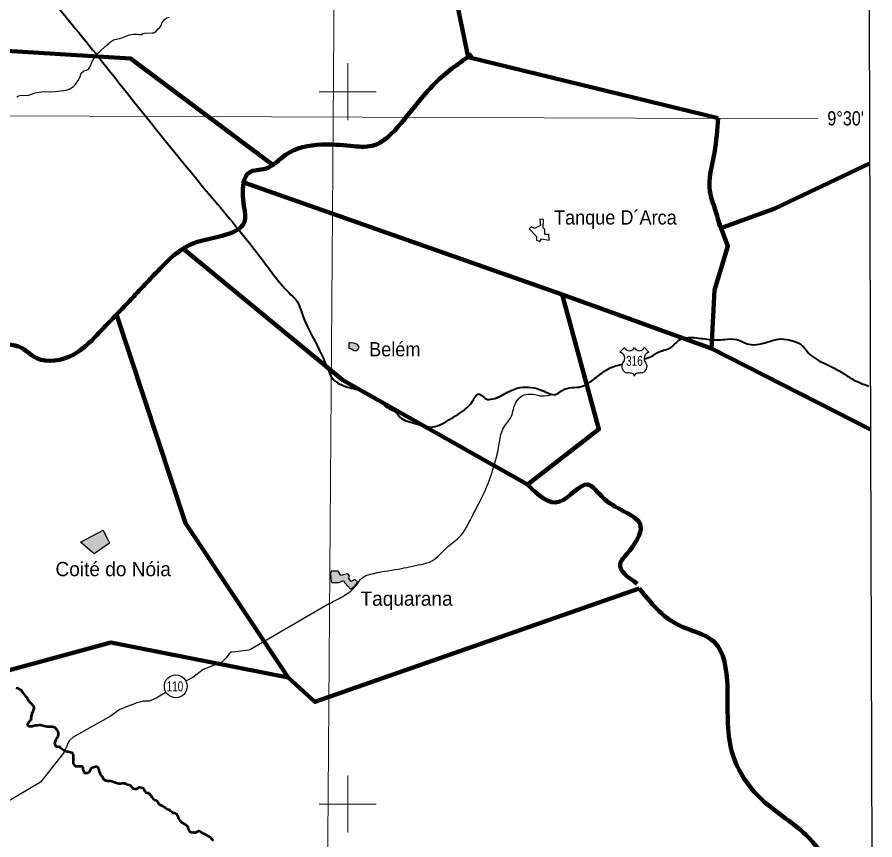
# Model space of a CAD drawing. Extents: x 553962 to 842807, y 8883888 to 9032388.
# Drawn here: x 763398 to 793496, y 8923744 to 8952617 of the extents above; entities that cross this region are included whole.
import ezdxf
from ezdxf.enums import TextEntityAlignment as Align

# ---------------------------------------------------------------- set-up
doc = ezdxf.new("R2010")
doc.units = 0
doc.header["$LTSCALE"] = 200
for name, color, linetype, lineweight in [('1', 7, 'Continuous', 13), ('12', 7, 'Continuous', 25), ('2', 7, 'Continuous', 13), ('21', 7, 'Continuous', 25), ('24', 7, 'Continuous', 25), ('3', 7, 'Continuous', 80), ('48', 7, 'Continuous', 25), ('9', 7, 'Continuous', 90)]:
    doc.layers.add(name, color=color, linetype=linetype, lineweight=lineweight)
doc.layers.add('41', color=7, linetype='Continuous')
doc.layers.add('46', color=7, linetype='Continuous')

msp = doc.modelspace()

# ---------------------------------------------------------------- hatches: boundary and pattern name
at = {"layer": '21'}
for points in [[(775339.3, 8941128.8), (775228, 8941177.1), (775095.1, 8941191.9), (775050.9, 8941185.2), (775036.1, 8941163.7), (775040.1, 8941107.3), (775033.4, 8941051), (775025.4, 8941018.8), (775064.3, 8940997.3), (775130, 8940970.5), (775194.4, 8940945), (775223.9, 8940916.8), (775309.8, 8940919.5), (775363.5, 8940965.1), (775403.7, 8941040.3)], [(765624.2, 8934185.8), (766418.4, 8934607.9), (766636, 8934155.3), (766095.9, 8933780)], [(774667, 8933172.8), (774418.6, 8933170.5), (774396, 8933082.4), (774400.5, 8932917.5), (774418.6, 8932822.7), (774445.7, 8932775.3), (774698.6, 8932779.8), (774850, 8932843), (774890.6, 8932773), (775098.4, 8932542.6), (775263.3, 8932657.8), (775353.6, 8932782), (775242.9, 8932881.4), (775123.2, 8932806.9), (775037.4, 8932913), (775055.5, 8933010.1), (775003.5, 8933075.6), (774888.3, 8933062.1), (774752.8, 8933019.2)]]:
    msp.add_hatch(color=256, dxfattribs=at).paths.add_polyline_path(points)

# ---------------------------------------------------------------- linework, layer by layer
at = {"layer": '1'}
msp.add_line((565315.3, 8949866.8), (791497.7, 8949052.2), dxfattribs=at)
msp.add_lwpolyline([(774987.1, 9020818), (774482.3, 8948876), (774053.6, 8890875.3)], dxfattribs=at)
at = {"layer": '12'}
for points in [[(774356.7, 8932040.9), (771581.7, 8930420.9), (771525.6, 8930405.7), (771061.8, 8930345.4), (770909, 8930335.5), (770822.1, 8930264.4), (770735, 8930137.2), (770571.4, 8929969.4), (770459.1, 8929908.4), (770367.4, 8929898.4), (769928.6, 8929726), (769560.8, 8929446.5), (769323.7, 8929324.5)], [(768612, 8928917.3), (768391.8, 8928786.5), (768305, 8928730.6), (768213.1, 8928695.1), (768044.7, 8928608.8), (767820.5, 8928609.2), (767703.2, 8928573.8), (767591.1, 8928548.5), (767438, 8928487.7), (767412.6, 8928487.7), (766978.9, 8928310.2), (766697.9, 8928101.9), (765365.5, 8927345.3), (765232.7, 8927233.5), (765181.3, 8927131.7), (765140.2, 8927029.9), (765099.1, 8926933.2), (765047.8, 8926826.3), (764310.7, 8925890.3), (764269.7, 8925824.2), (764213.5, 8925763.2), (763095.4, 8925103)]]:
    msp.add_lwpolyline(points, dxfattribs=at)
at = {"layer": '12', "lineweight": 40}
for points in [[(761549.2, 8957020.4), (762383.1, 8955993.9), (763257, 8954902.9), (764214.4, 8953717.3), (766168.2, 8951324.4), (767086.6, 8950171.6), (770317.8, 8946184.2), (771971, 8944146), (773006.3, 8942876.2), (773223.4, 8942642.3), (773373.7, 8942274.8), (774008.3, 8940921.5), (774359, 8940136.3), (774475.8, 8939919.1), (774642.8, 8939785.5), (774893.3, 8939668.5), (775511.2, 8939484.7), (775928.6, 8939267.5), (776078.9, 8939184), (776379.5, 8938916.7), (776680.1, 8938749.6), (776830.4, 8938582.6), (777398.1, 8938348.7), (777899.1, 8938231.7), (778550.4, 8938482.3), (779134.8, 8938866.6), (779452.1, 8939250.8), (779569, 8939384.5), (779685.9, 8939351.1), (779852.9, 8939217.4), (780086.7, 8939217.4), (780604.3, 8939451.3), (781055.2, 8939618.4), (781439.3, 8939618.4), (781823.3, 8939518.1), (782090.5, 8939401.2), (782290.9, 8939367.8), (782524.7, 8939518.1), (782858.7, 8939618.4), (783192.6, 8939651.8), (783509.9, 8939818.9), (783910.7, 8940119.6), (784278.1, 8940336.8), (784625.2, 8940434.5)], [(785398.3, 8940626.9), (785647.4, 8940704.3), (785931.2, 8940871.4), (786332, 8941021.8), (786615.9, 8941272.4), (787083.5, 8941372.6), (787684.6, 8941305.8), (788219, 8941305.8), (788636.5, 8941305.8), (789070.6, 8941138.7), (789438, 8941138.7), (789855.5, 8941255.7)], [(789855.5, 8941255.7), (790222.9, 8941322.5), (790556.8, 8941272.4), (790907.5, 8941122), (791208.1, 8940787.9), (791792.6, 8940437), (792326.9, 8940153), (792694.3, 8939919.1), (793278.8, 8939668.5)]]:
    msp.add_spline(points, degree=3, dxfattribs=at)
at = {"layer": '12'}
msp.add_spline([(774356.7, 8932040.9), (774893.9, 8932329.3), (775282.4, 8932656.4), (775507.2, 8932942.7), (775793.5, 8933065.3), (776774.8, 8933249.3), (777572.2, 8933412.9), (777960.7, 8933535.6), (778451.3, 8933985.3), (778901.1, 8934353.3), (779350.9, 8935068.9), (779841.6, 8936050.3), (780127.8, 8936847.6), (780291.4, 8937501.9), (780393.6, 8938033.4), (780516.3, 8938278.8), (780720.7, 8938565), (780863.8, 8939014.8), (781047.8, 8939280.6), (781477.2, 8939382.8), (781824.8, 8939321.5), (782163.7, 8939377.8)], degree=3, dxfattribs=at)
at = {"layer": '2'}
for p, q in [((775000, 8949000), (775000, 8951000)), ((774000, 8950000), (776000, 8950000)), ((775000, 8924000), (775000, 8926000)), ((774000, 8925000), (776000, 8925000))]:
    msp.add_line(p, q, dxfattribs=at)
at = {"layer": '21'}
for points in [[(782068, 8944791.6), (782057.7, 8944984.8), (781912.3, 8944989.1), (781919.3, 8945159.5), (781854.8, 8945223), (781863, 8945498.7), (781863.2, 8945516.3), (781743, 8945525.3), (781760.5, 8945307), (781556.3, 8945201.7), (781439.1, 8945255.8), (781368.2, 8945189.1), (781618.3, 8944920.1), (781624.3, 8944789.7), (781739.1, 8944748.1), (781797.8, 8944840.2)], [(775339.3, 8941128.8), (775228, 8941177.1), (775095.1, 8941191.9), (775050.9, 8941185.2), (775036.1, 8941163.7), (775040.1, 8941107.3), (775033.4, 8941051), (775025.4, 8941018.8), (775064.3, 8940997.3), (775130, 8940970.5), (775194.4, 8940945), (775223.9, 8940916.8), (775309.8, 8940919.5), (775363.5, 8940965.1), (775403.7, 8941040.3)], [(765624.2, 8934185.8), (766418.4, 8934607.9), (766636, 8934155.3), (766095.9, 8933780)], [(774667, 8933172.8), (774418.6, 8933170.5), (774396, 8933082.4), (774400.5, 8932917.5), (774418.6, 8932822.7), (774445.7, 8932775.3), (774698.6, 8932779.8), (774850, 8932843), (774890.6, 8932773), (775098.4, 8932542.6), (775263.3, 8932657.8), (775353.6, 8932782), (775242.9, 8932881.4), (775123.2, 8932806.9), (775037.4, 8932913), (775055.5, 8933010.1), (775003.5, 8933075.6), (774888.3, 8933062.1), (774752.8, 8933019.2)]]:
    msp.add_lwpolyline(points, close=True, dxfattribs=at)
at = {"layer": '24'}
for points in [[(768186, 8952066.6), (768216.9, 8952077), (768276.8, 8952125.6), (768349.5, 8952201.8), (768405, 8952249), (768448.6, 8952322.2), (768492.5, 8952435.6), (768528.1, 8952482.7), (768574.2, 8952530.8), (768613.3, 8952565.3), (768657.1, 8952591.4), (768749.7, 8952621.2)], [(763389.4, 8949825.8), (763440.7, 8949858.6), (763555.2, 8949879.5), (763767.2, 8949868.9), (763967.1, 8949936), (764029.1, 8949960.5), (764080.2, 8949974.5), (764174.7, 8949982.8), (764331.6, 8950003.9), (764575.5, 8950000), (764735.9, 8950008.2), (765114.3, 8950055), (765220.7, 8950084.3), (765370.3, 8950178.2), (765443.7, 8950253.3), (765542.9, 8950393), (765598.6, 8950494.9), (765646.8, 8950651.1), (765735.2, 8950727.6), (765832.8, 8950754), (765891.8, 8950782.4), (765926.9, 8950823), (765961.1, 8950880.3), (765989.9, 8950971.4), (766040.9, 8951087.5), (766108.1, 8951189.6), (766159.2, 8951254.6), (766195.3, 8951316.5), (766224.6, 8951348.1), (766309.2, 8951420.9), (766494.8, 8951595.8), (766626.9, 8951699.9), (766678.8, 8951749.2), (766729.6, 8951787.4), (766780.6, 8951816.9), (766824.2, 8951832), (766991.9, 8951866.2), (767075.7, 8951890.5), (767194, 8951942.7), (767344.8, 8951998.9), (767476.1, 8952017.3), (767610.5, 8952017.2), (767669.1, 8952003.5), (767722.7, 8952005.2), (767758.5, 8952013.4), (767805.8, 8952043.2), (767869.4, 8952058.6), (768139.3, 8952060.8), (768186, 8952066.6), (768186, 8952066.6)]]:
    msp.add_lwpolyline(points, dxfattribs=at)
at = {"layer": '24', "lineweight": 53}
for points in [[(763354.1, 8929082.6), (763435.4, 8929061.7), (763486.1, 8929035.9)], [(763486.1, 8929035.9), (763536.7, 8928999.9), (763571.9, 8928943.7), (763591.9, 8928897.7), (763647.5, 8928846.4), (763692.9, 8928790.1), (763733.3, 8928743.9), (763773.5, 8928682.6), (763823.8, 8928600.8), (763884.3, 8928523.9), (763945, 8928462.4), (763980.3, 8928426.6), (763979.9, 8928365.4), (763959.1, 8928294.2), (763948.5, 8928233.2), (763917.6, 8928182.4), (763896.8, 8928116.4), (763881.7, 8928039.6), (763887.8, 8927997.1), (763875.7, 8927954.6), (763787.7, 8927848.4), (763757.4, 8927796.8), (763757.1, 8927770.9), (763812.8, 8927734.9), (763868.7, 8927729.4), (763929.7, 8927729), (763996.1, 8927759.2), (764036.4, 8927766.4), (764108.1, 8927773.7), (764169.1, 8927778.4), (764218.3, 8927775.5), (764294.1, 8927751.2), (764342.7, 8927748.2), (764391.2, 8927736), (764445.8, 8927723.9), (764524.6, 8927723.9), (764588.3, 8927723.9), (764639.8, 8927717.8), (764703.5, 8927699.6), (764727.9, 8927673), (764763.2, 8927637.1), (764793.5, 8927596.1), (764823.7, 8927550.1), (764838.5, 8927488.9), (764843.2, 8927427.7), (764827.6, 8927376.9), (764806.6, 8927326.2), (764773.2, 8927283.7), (764749, 8927229), (764721.7, 8927174.4), (764712.6, 8927134.9), (764715.6, 8927107.6), (764746, 8927043.8), (764764.1, 8927025.8), (764815, 8927025.5), (764876, 8927020), (764921.4, 8926973.9), (764987.2, 8926927.6), (765032.8, 8926891.6), (765088.6, 8926870.9), (765139.3, 8926850.2), (765190.1, 8926844.8), (765240.9, 8926834.3), (765311.9, 8926808.3), (765352.4, 8926772.4)], [(765352.4, 8926772.4), (765367.2, 8926706.1), (765366.8, 8926655.2), (765366.3, 8926578.8), (765365.7, 8926487.1), (765365.2, 8926420.9), (765400.5, 8926379.9), (765451.1, 8926333.7), (765501.9, 8926328.3), (765557.8, 8926327.9), (765613.8, 8926327.6), (765674.9, 8926332.3), (765705.1, 8926286.3), (765704.7, 8926235.3), (765714.4, 8926169), (765744.7, 8926128.1), (765774.9, 8926082.1), (765830.9, 8926097), (765881.8, 8926096.7), (765943.1, 8926137), (765974, 8926197.9), (765994.7, 8926243.7), (766025.5, 8926284.2), (766076.5, 8926299.2), (766142.7, 8926314), (766193.5, 8926313.7), (766254.2, 8926257.3), (766269, 8926190.9), (766273.7, 8926140), (766298.8, 8926088.9), (766349.1, 8926007.1), (766389.4, 8925950.8), (766419.5, 8925884.3), (766465, 8925853.5), (766515.7, 8925827.7), (766571.5, 8925812.1), (766622.4, 8925811.7)], [(766622.4, 8925811.7), (766673.3, 8925811.4), (766724.1, 8925806), (766785, 8925785.2), (766850.9, 8925754.2), (766922, 8925733.4), (766972.7, 8925717.8), (767028.7, 8925722.5), (767084.7, 8925732.4), (767161, 8925731.9), (767206.6, 8925706.1), (767272.6, 8925685.3), (767328.4, 8925674.8), (767379.1, 8925649), (767434.6, 8925582.4), (767475, 8925541.4), (767525.8, 8925536), (767586.9, 8925535.6), (767632.8, 8925555.7), (767694.1, 8925590.9), (767755, 8925580.3), (767805.8, 8925574.9), (767846.2, 8925518.6), (767876.2, 8925452.2), (767916.6, 8925411.2), (767967.4, 8925395.6), (768018.2, 8925390.2), (768038.2, 8925344.2), (768098.9, 8925287.8), (768139.2, 8925226.4), (768169.3, 8925180.4), (768214.9, 8925149.5), (768286, 8925128.7), (768336.4, 8925062.1), (768361.4, 8925005.9), (768417.1, 8924969.9), (768498.3, 8924938.8), (768548.9, 8924907.9), (768609.7, 8924866.8), (768655.2, 8924836), (768711, 8924810.1), (768766.8, 8924779.2), (768817.3, 8924733), (768852.6, 8924692.1), (768903.5, 8924691.7), (768984.6, 8924650.5), (769014.8, 8924604.4), (769039.9, 8924558.4), (769054.7, 8924497.2), (769108.6, 8924423.6), (769140.5, 8924391.6), (769140.5, 8924381), (769206.3, 8924343.4), (769256.8, 8924302.3), (769308.2, 8924278.5), (769355, 8924247.3), (769386.2, 8924192.6), (769401.8, 8924137.9), (769425.2, 8924075.5), (769464.2, 8924028.6), (769534.3, 8924005.2), (769573.3, 8924013), (769596.7, 8923997.4), (769661.7, 8924004.3), (769728.1, 8924039.5)], [(769728.1, 8924039.5), (769779, 8924054.5), (769829.7, 8924033.8), (769870.2, 8924003), (769936.1, 8923972), (770002, 8923935.9), (770062.8, 8923899.8), (770113.4, 8923869), (770169.1, 8923832.9), (770239.8, 8923761.2), (770275.1, 8923704.9)]]:
    msp.add_lwpolyline(points, dxfattribs=at)
at = {"layer": '3', "lineweight": 25}
msp.add_lwpolyline([(563033.9, 9026438.8), (793061.1, 9026438.8), (793495.6, 8889836.8), (563468.3, 8889836.8)], close=True, dxfattribs=at)
at = {"layer": '48'}
for p, q in [((784549.3, 8940864.5), (784709.3, 8941024.4)), ((785408.6, 8941024.4), (785568.6, 8940864.5))]:
    msp.add_line(p, q, dxfattribs=at)
msp.add_circle((768965.2, 8929131), 401.3, dxfattribs=at)
for centre, radius, start, end in [((784884.1, 8941091.4), 187.2, 200.95927, 339.04073), ((785233.8, 8941091.4), 187.2, 200.95927, 339.04073), ((784487.3, 8940642.7), 230.3, 317.5721, 74.36886), ((785630.6, 8940642.7), 230.3, 105.62774, 222.4279), ((784840.8, 8940357.5), 224.7, 144.73733, 264.65778), ((785277.1, 8940357.5), 224.7, 275.34222, 35.26267), ((784818.8, 8939544.1), 589.7, 72.89371, 89.90057), ((784964.6, 8940017.4), 94.4, 357.69345, 72.92955), ((785153.3, 8940017.4), 94.4, 107.07045, 182.30655), ((785299, 8939544.1), 589.7, 90.09943, 107.10629)]:
    msp.add_arc(centre, radius, start, end, dxfattribs=at)
at = {"layer": '9'}
for p, q in [((779222.2, 8951211.2), (787995, 8949076.7)), ((782526.1, 8942878.5), (771355.2, 8946811.1)), ((787760.8, 8940985.8), (793341.9, 8938141)), ((787760.8, 8940985.8), (793341.9, 8938141))]:
    msp.add_line(p, q, dxfattribs=at)
for points in [[(779222.2, 8951211.2), (778550.6, 8954494.6), (777527.6, 8956664.6), (776378.1, 8958732.8), (766764.9, 8967647.5)], [(750519.5, 8951321.2), (753181.6, 8952045.1), (767371, 8951165.8), (772338.7, 8947456.5)], [(793312.2, 8947480.4), (789981.2, 8945899), (788096.9, 8945214.4)], [(793312.2, 8947480.4), (789981.2, 8945899), (788096.9, 8945214.4)], [(782526.1, 8942878.5), (787760.8, 8940985.8), (787869.6, 8943035.4), (788337.5, 8944573.8), (788005.2, 8945458.5)], [(769262.3, 8944467.1), (774822.1, 8939873.5), (781306.6, 8936216.9)], [(781336.6, 8936240), (783812, 8938154.4), (782526.1, 8942878.5)], [(766889.5, 8942185.1), (769307.8, 8934856.9), (772905.7, 8929437.8)], [(785228, 8932570.7), (773847.7, 8928582.9), (772905.7, 8929437.8), (766683.7, 8930666.8), (762959.3, 8929647.4)]]:
    msp.add_lwpolyline(points, dxfattribs=at)
for points in [[(779358.3, 8951316.5), (778152, 8950383.2), (776870.5, 8948893), (775858.2, 8948102.8), (775096.9, 8948098.3), (774081.6, 8948143.1), (772814, 8947781.5), (772105.2, 8947296.6), (771547.4, 8947166.9), (771322, 8946330.6), (771374.4, 8945875.5), (771395.1, 8945546.1), (769593.3, 8944681.6), (768541.6, 8943918.8), (767488.3, 8942812.2), (766189.2, 8941452.3), (765366.7, 8940769), (764084.5, 8940646.2), (763321.5, 8941097.2), (762890.2, 8941044.2), (762866.3, 8940639.2), (762461.9, 8940181.4), (761397.4, 8939821), (760940.2, 8939919.5), (760875, 8939930.2)], [(788054.5, 8945281.7), (787894.4, 8945856.5), (787708.9, 8946496.2), (787865.6, 8947860), (787995, 8949076.7)], [(785158.1, 8932730.4), (784558.7, 8933436), (784793.4, 8933780.1), (785277.2, 8934758.1), (784000.5, 8935708.8), (783414, 8936210.6), (782437.6, 8935613.1), (781306.6, 8936216.9)], [(785228, 8932570.7), (786596.9, 8931287.5), (787857.2, 8930689.4), (788320, 8929128.3), (788478.3, 8926833.8), (789430.8, 8925249.3), (791075.7, 8923916.1), (791912, 8922868)]]:
    msp.add_spline(points, degree=3, dxfattribs=at)

# ---------------------------------------------------------------- texts
at = {"layer": '41', "width": 0.95}
for s, p in [('Tanque D´Arca', (782236.3, 8945338.2)), ('Belém', (775750, 8940712.5))]:
    msp.add_text(s, height=500, dxfattribs=at).set_placement(p)
at = {"layer": '41'}
for s, p in [('Coité do Nóia', (764742.7, 8932997.3)), ('Taquarana', (775446.3, 8931959.3))]:
    msp.add_text(s, height=500, dxfattribs=at).set_placement(p)
at = {"layer": '46', "width": 0.85}
msp.add_text("9°30'", height=500, dxfattribs=at).set_placement((792469.3, 8948815.9), align=Align.CENTER)
at = {"layer": '48', "width": 0.75}
for s, p in [('316', (785058.5, 8940380.2)), ('110', (768933.5, 8928957.7))]:
    msp.add_text(s, height=350, dxfattribs=at).set_placement(p, align=Align.CENTER)

doc.saveas('drawing.dxf')
